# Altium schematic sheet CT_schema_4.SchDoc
size 279 x 144 mm
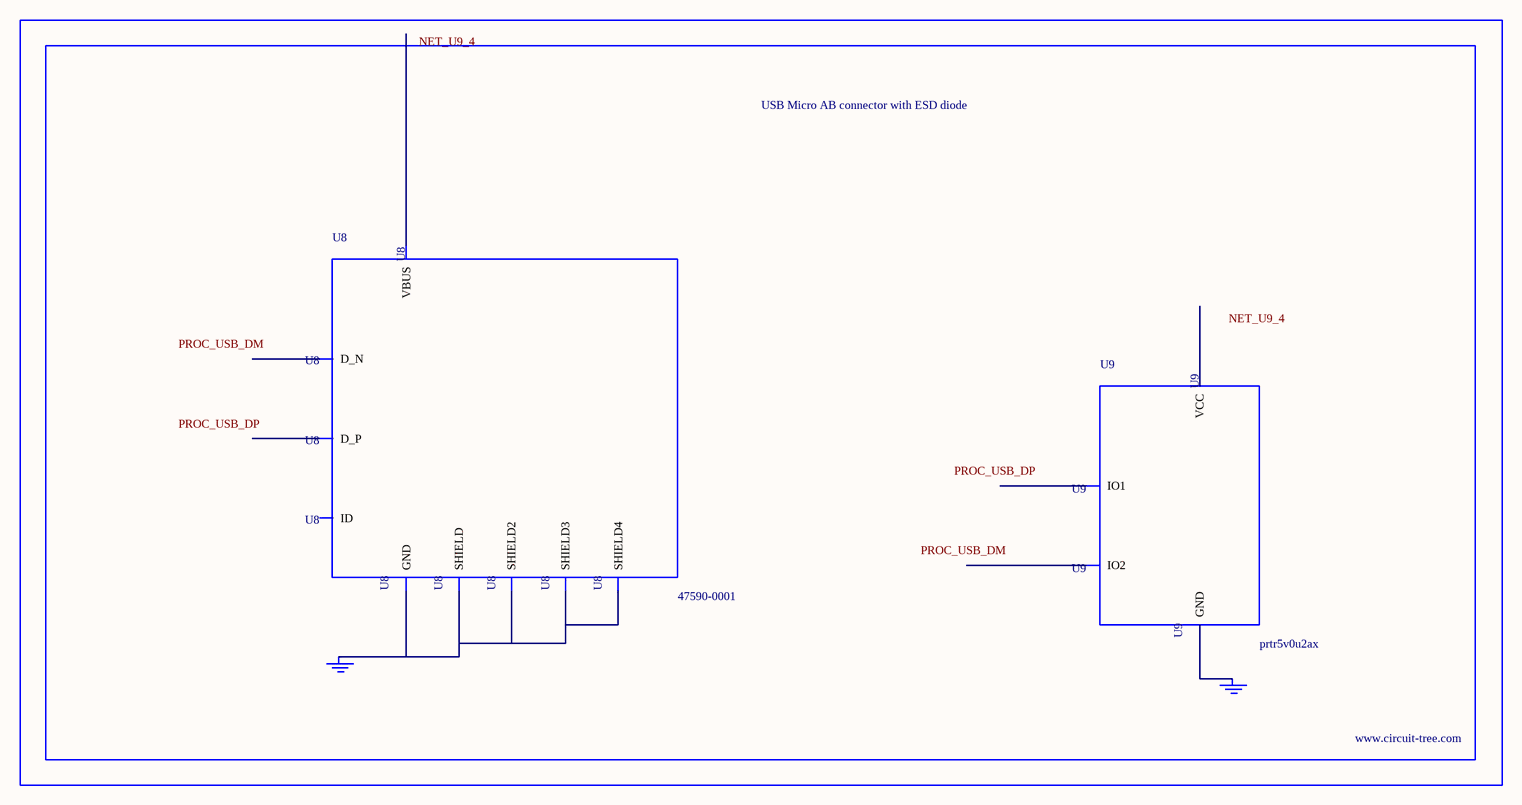
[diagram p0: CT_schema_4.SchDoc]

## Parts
BORDER3  (no value)
GND_INSTANCE_3_0  (no value)
GND_INSTANCE_3_1  (no value)
U8  47590-0001  [MICRO_USB_AB]
U9  prtr5v0u2ax  [SOT143B]

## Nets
NetGND_INSTANCE_3_0_0: GND_INSTANCE_3_0.0(GND) U8.5(GND) U8.6(SHIELD) U8.7(SHIELD2) U8.8(SHIELD3) U8.9(SHIELD4)
NetGND_INSTANCE_3_1_0: GND_INSTANCE_3_1.0(GND) U9.1(GND)

Not connected (* = marked no-connect by the designer): U8 1(VBUS) 2(D_N) 3(D_P) 4(ID); U9 2(IO1) 3(IO2) 4(VCC)

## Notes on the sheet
- Labels drawn without touching a wire or pin: NET_U9_4, PROC_USB_DM, PROC_USB_DP

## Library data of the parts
BORDER3 = BORDER_PAGE3
GND_INSTANCE_3_0 GND_INSTANCE_3_1 = GND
